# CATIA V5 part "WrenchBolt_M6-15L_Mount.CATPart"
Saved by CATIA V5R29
Part number: WrenchBolt_M6-15L_Mount
Bounding box of the stored display mesh (mm): x -5.11 to 5.11, y -5.11 to 5.11, z -15 to 6
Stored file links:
  C:\Users\Administrator\Desktop\프로젝트\Boxfold\Bolt\WrenchBolt_M6-15L_Mount.CATPart
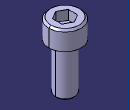
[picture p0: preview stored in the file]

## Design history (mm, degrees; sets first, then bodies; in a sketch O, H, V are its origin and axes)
Body1 (main body)
  Sketch1 on xy-plane, origin (0, 0, 0), H (1, 0, 0), V (0, 1, 0)
    circle A1 centre (0, 0) radius 5.11
    radius A1 = 5.11
  Pad1: profile Sketch1, direction (0, 0, 1), length 6
  Sketch2 on start face of Pad1, origin (0, 0, 0), H (1, 0, 0), V (0, -1, 0)
    circle A1 centre (0, 0) radius 3
    radius A1 = 3
  Pad2: profile Sketch2, direction (0, 0, -1), length 15
  Sketch3 on end face of Pad1, origin (0, 0, 6), H (1, 0, 0), V (0, 1, 0)
    point P1 (2.5475, 0)
    construction circle A1 centre (0, 0) radius 2.9416
    construction circle A2 centre (0, 0) radius 2.5475
    point P2 (2.5475, -1.4708)
    point P3 (2.5475, 1.4708)
    point P4 (0, 2.9416)
    point P5 (-2.5475, 1.4708)
    point P6 (-2.5475, -1.4708)
    point P7 (0, -2.9416)
    line L1 (2.5475, -1.4708) -> (2.5475, 1.4708)
    line L2 (2.5475, 1.4708) -> (0, 2.9416)
    line L3 (0, 2.9416) -> (-2.5475, 1.4708)
    line L4 (-2.5475, 1.4708) -> (-2.5475, -1.4708)
    line L5 (-2.5475, -1.4708) -> (0, -2.9416)
    line L6 (0, -2.9416) -> (2.5475, -1.4708)
    construction line L7 (0, 0) -> (2.5475, 0)
    radius A2 = 2.5475
    coincidence: A1 P2, A1 P3, A1 P4, A1 P5, A1 P6, A1 P7
    tangency: A2 L1, A2 L2, A2 L3, A2 L4, A2 L5, A2 L6
    midpoint: P1 L1
    horizontal: L7 H
  Pocket1: profile Sketch3, direction (0, 0, -1), length 3
  Thread1: "M6", diameter 6, depth 15, pitch 1, on face of Pad2 from Sketch2.A1, from end face of Pad2
  Chamfer1: length 0.6, angle 45, on end face of Pad2; edge [face of Pad1 from Sketch1.A1 | end face of Pad1]
  Fillet1: radius 0.25, on edge [start face of Pad1 | face of Pad2 from Sketch2.A1]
